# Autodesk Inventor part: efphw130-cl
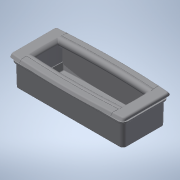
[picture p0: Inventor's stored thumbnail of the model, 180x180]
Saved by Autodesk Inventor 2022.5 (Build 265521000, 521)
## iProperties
Created: 2016-12
Part Number: efphw130-cl
Material: 一般
Document SubType Name: Modeling
Designer: imaocorp
Density: 1 g/cm^3
Appearance: 既定
Author: imaocorp
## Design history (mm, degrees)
node "efphw130-cl.x_t1"
node "Part26"
node "Base1"
